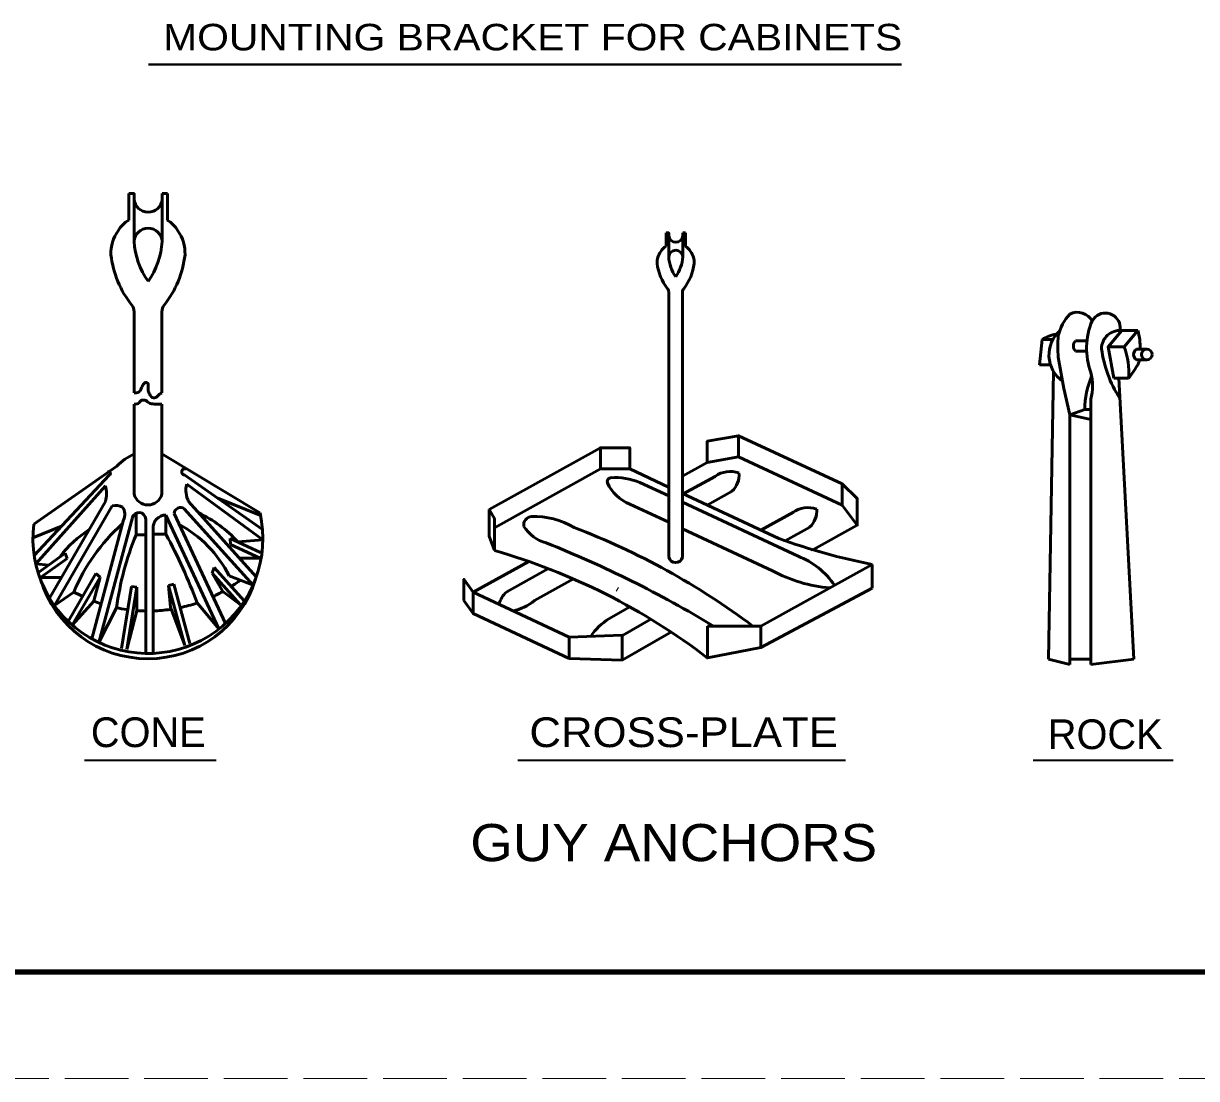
# Model space of a CAD drawing. Extents: x 12366 to 13046, y 9129 to 9570.
# Drawn here: x 12526.1 to 12636.6, y 9129.5 to 9228.9 of the extents above; entities that cross this region are included whole.
import ezdxf
from ezdxf.enums import TextEntityAlignment as Align

# ---------------------------------------------------------------- set-up
doc = ezdxf.new("R2010")
doc.units = 0
doc.linetypes.add('LONG_DASHED', pattern=[7.5, 6, -1.5])
doc.layers.add('1', color=7, linetype='Continuous', lineweight=53)
doc.layers.add('61', color=7, linetype='Continuous', lineweight=35)

msp = doc.modelspace()

# ---------------------------------------------------------------- linework, layer by layer
at = {"layer": '1', "lineweight": 40}
msp.add_line((12537.897, 9225.048), (12608.824, 9225.048), dxfattribs=at)
at = {"layer": '1'}
for p, q in [((12536.03, 9212.87), (12536.03, 9210.37)), ((12539.168, 9212.363), (12539.168, 9212.87)), ((12539.168, 9212.87), (12539.668, 9212.87)), ((12539.668, 9212.87), (12539.668, 9210.37)), ((12536.53, 9212.369), (12536.53, 9208.369)), ((12539.168, 9212.363), (12539.168, 9208.363)), ((12586.645, 9209.166), (12586.645, 9207.916)), ((12586.895, 9208.916), (12586.895, 9206.916)), ((12588.215, 9208.913), (12588.215, 9209.166)), ((12588.215, 9209.166), (12588.465, 9209.166)), ((12588.215, 9208.913), (12588.215, 9206.913)), ((12588.465, 9209.166), (12588.465, 9207.916)), ((12586.895, 9203.606), (12586.895, 9178.606)), ((12588.203, 9203.606), (12588.203, 9178.606)), ((12536.53, 9201.748), (12536.53, 9194.107)), ((12539.146, 9201.748), (12539.146, 9194.107)), ((12622.067, 9199.115), (12621.828, 9196.734)), ((12623.067, 9199.115), (12622.067, 9199.115)), ((12626.299, 9198.994), (12625.223, 9198.994)), ((12626.227, 9198.037), (12625.223, 9198.037)), ((12631.955, 9198.21), (12630.955, 9198.21)), ((12622.823, 9196.734), (12621.828, 9196.734)), ((12631.955, 9197.21), (12630.955, 9197.21)), ((12622.678, 9169.017), (12623.151, 9196.113)), ((12629.317, 9195.482), (12628.817, 9195.482)), ((12630.704, 9169.018), (12629.317, 9195.482)), ((12629.317, 9195.482), (12630.22, 9195.482)), ((12536.529, 9184.541), (12536.529, 9193.041)), ((12539.147, 9184.541), (12539.147, 9193.041)), ((12626.678, 9168.517), (12626.678, 9193.517)), ((12624.678, 9168.517), (12624.678, 9192.017)), ((12624.678, 9192.017), (12626.678, 9191.592)), ((12593.485, 9190.065), (12603.228, 9185.522)), ((12580.469, 9188.93), (12569.973, 9183.112)), ((12539.131, 9188.351), (12548.363, 9182.804)), ((12590.53, 9187.544), (12588.203, 9186.255)), ((12590.53, 9187.544), (12593.485, 9188.065)), ((12593.485, 9188.065), (12603.228, 9183.522)), ((12534.891, 9187.204), (12527.083, 9181.737)), ((12534.181, 9186.351), (12527.117, 9178.777)), ((12541.315, 9186.351), (12548.632, 9181.228)), ((12580.469, 9186.93), (12570.473, 9181.389)), ((12583.219, 9186.93), (12586.889, 9185.219)), ((12591.258, 9186.233), (12588.268, 9184.575)), ((12533.831, 9185.351), (12527.265, 9177.988)), ((12541.484, 9185.483), (12548.665, 9180.265)), ((12584.177, 9185.656), (12586.906, 9184.383)), ((12603.228, 9185.522), (12603.228, 9183.522)), ((12548.37, 9182.583), (12544.413, 9184.182)), ((12588.203, 9184.606), (12597.266, 9180.379)), ((12592.864, 9184.836), (12590.509, 9183.531)), ((12533.831, 9183.851), (12528.575, 9174.748)), ((12534.466, 9183.452), (12529.037, 9174.049)), ((12541.261, 9183.179), (12547.737, 9175.987)), ((12541.665, 9183.851), (12548.034, 9176.778)), ((12583.226, 9183.617), (12586.895, 9181.905)), ((12588.185, 9183.787), (12599.079, 9178.707)), ((12535.538, 9182.125), (12532.536, 9170.924)), ((12536.378, 9182.366), (12533.218, 9170.573)), ((12536.711, 9180.711), (12536.711, 9182.816)), ((12537.622, 9182.214), (12537.622, 9169.541)), ((12539.532, 9182.588), (12544.528, 9171.873)), ((12540.292, 9182.731), (12545.127, 9172.365)), ((12598.641, 9182.867), (12595.576, 9181.168)), ((12526.981, 9180.44), (12529.689, 9181.534)), ((12536.711, 9180.711), (12537.622, 9180.711)), ((12538.332, 9181.271), (12538.332, 9169.541)), ((12588.203, 9181.296), (12596.675, 9177.345)), ((12600.189, 9181.438), (12597.883, 9180.16)), ((12545.587, 9180.387), (12548.439, 9179.057)), ((12545.587, 9180.387), (12545.614, 9179.822)), ((12545.614, 9179.822), (12548.408, 9178.519)), ((12548.665, 9180.265), (12546.292, 9180.058)), ((12527.426, 9177.101), (12530.05, 9179.007)), ((12527.72, 9176.697), (12530.214, 9178.508)), ((12530.05, 9179.007), (12530.214, 9178.508)), ((12548.408, 9178.519), (12546.466, 9178.519)), ((12527.265, 9177.988), (12528.498, 9177.88)), ((12544.07, 9177.646), (12543.882, 9177.108)), ((12544.07, 9177.646), (12546.901, 9174.501)), ((12575.567, 9177.535), (12571.63, 9175.353)), ((12606.057, 9177.935), (12606.057, 9175.685)), ((12527.72, 9176.697), (12529.73, 9176.697)), ((12530.331, 9172.558), (12532.939, 9177.074)), ((12530.709, 9172.212), (12533.32, 9176.733)), ((12533.32, 9176.733), (12532.725, 9174.514)), ((12532.939, 9177.074), (12533.32, 9176.733)), ((12543.882, 9177.108), (12546.53, 9174.167)), ((12544.892, 9175.376), (12543.882, 9177.108)), ((12547.737, 9175.987), (12545.484, 9176.872)), ((12577.936, 9176.561), (12574.262, 9174.525)), ((12529.037, 9174.049), (12530.858, 9175.328)), ((12536.278, 9175.861), (12535.35, 9170.003)), ((12536.772, 9175.783), (12535.844, 9169.924)), ((12536.278, 9175.861), (12536.772, 9175.783)), ((12536.772, 9175.783), (12536.772, 9173.562)), ((12540.266, 9176.079), (12539.783, 9175.949)), ((12539.783, 9175.949), (12541.299, 9170.292)), ((12539.783, 9175.949), (12539.961, 9173.915)), ((12540.266, 9176.079), (12541.766, 9170.48)), ((12546.53, 9174.167), (12544.892, 9175.376)), ((12568.459, 9175.31), (12577.522, 9171.084)), ((12568.459, 9175.31), (12568.459, 9173.31)), ((12530.709, 9172.212), (12532.753, 9174.49)), ((12544.528, 9171.873), (12542.47, 9174.303)), ((12533.218, 9170.573), (12534.879, 9173.845)), ((12535.844, 9169.924), (12536.772, 9173.562)), ((12541.299, 9170.292), (12539.961, 9173.915)), ((12583.226, 9173.941), (12581.27, 9172.809)), ((12585.214, 9172.781), (12582.544, 9171.235)), ((12595.562, 9172.118), (12595.562, 9170.118)), ((12577.522, 9171.084), (12582.519, 9171.258)), ((12577.522, 9171.084), (12577.522, 9169.084)), ((12587.157, 9171.596), (12582.519, 9168.909)), ((12582.519, 9171.258), (12582.519, 9168.909)), ((12577.522, 9169.084), (12582.519, 9168.909)), ((12622.678, 9169.017), (12624.678, 9168.517)), ((12624.678, 9169.017), (12626.678, 9169.017)), ((12626.678, 9168.517), (12630.704, 9169.018))]:
    msp.add_line(p, q, dxfattribs=at)
at = {"layer": '1', "lineweight": 13}
for p, q in [((12600.486, 9179.316), (12600.324, 9179.222)), ((12581.956, 9175.403), (12582.168, 9175.746))]:
    msp.add_line(p, q, dxfattribs=at)
at = {"layer": '1', "lineweight": 35}
for p, q in [((12531.844, 9159.487), (12544.266, 9159.487)), ((12572.686, 9159.487), (12603.553, 9159.487)), ((12621.245, 9159.487), (12634.419, 9159.487))]:
    msp.add_line(p, q, dxfattribs=at)
at = {"layer": '1'}
for points in [[(12536.53, 9212.369), (12536.53, 9212.87), (12536.03, 9212.87)], [(12586.895, 9208.916), (12586.895, 9209.166), (12586.645, 9209.166)], [(12628.817, 9195.482), (12628.296, 9198.436), (12629.796, 9198.436), (12631.082, 9199.968)], [(12628.296, 9198.436), (12629.582, 9199.968), (12631.082, 9199.968)], [(12624.678, 9192.017), (12624.123, 9194.513), (12623.602, 9197.468)], [(12624.678, 9192.017), (12626.088, 9192.53), (12626.678, 9192.53)], [(12590.53, 9187.544), (12590.53, 9189.544), (12593.485, 9190.065), (12593.485, 9188.065)], [(12603.236, 9185.116), (12603.228, 9185.522), (12604.666, 9184.133), (12604.666, 9181.633)], [(12569.973, 9183.112), (12570.473, 9182.246), (12570.473, 9179.246)], [(12569.973, 9183.112), (12569.973, 9180.612), (12570.473, 9179.246)], [(12603.228, 9183.522), (12604.666, 9181.633), (12600.486, 9179.316)], [(12539.532, 9182.588), (12539.532, 9180.782), (12538.332, 9180.782)], [(12573.706, 9178.219), (12568.459, 9175.31), (12567.598, 9176.539), (12567.598, 9174.539)], [(12606.057, 9177.935), (12595.562, 9172.118), (12590.562, 9172.118)], [(12590.562, 9172.118), (12590.562, 9169.118), (12595.562, 9170.118), (12606.057, 9175.685)], [(12567.598, 9174.539), (12568.459, 9173.31), (12577.522, 9169.084)]]:
    msp.add_lwpolyline(points, dxfattribs=at)
msp.add_lwpolyline([(12583.219, 9186.93), (12583.219, 9188.93), (12580.469, 9188.93), (12580.469, 9186.93)], close=True, dxfattribs=at)
msp.add_circle((12631.936, 9197.714), 0.5, dxfattribs=at)
for centre, radius, start, end in [((12537.849, 9212.441), 1.321, 183.14868, 356.60343), ((12537.296, 9208.104), 2.595, 119.19068, 150.80932), ((12537.849, 9208.29), 1.321, 3.15687, 176.59703), ((12538.38, 9208.104), 2.595, 29.19068, 60.80932), ((12538.005, 9207.241), 3.659, 144.42176, 182.06662), ((12543.742, 9208.792), 7.224, 183.35766, 215.34932), ((12531.957, 9208.786), 7.224, 324.65068, 356.64234), ((12537.67, 9207.241), 3.659, 357.93338, 35.57824), ((12587.555, 9208.952), 0.661, 183.14868, 356.60343), ((12587.633, 9206.352), 1.829, 144.42176, 182.06662), ((12587.278, 9206.783), 1.298, 119.19068, 150.80932), ((12587.555, 9206.876), 0.661, 3.15687, 176.59703), ((12587.82, 9206.783), 1.298, 29.19068, 60.80932), ((12587.466, 9206.352), 1.829, 357.93338, 35.57824), ((12543.627, 9208.177), 9.339, 186.56595, 218.44896), ((12532.049, 9208.177), 9.339, 321.55104, 353.43405), ((12590.444, 9206.82), 4.669, 186.56595, 218.44896), ((12590.501, 9207.127), 3.612, 183.35766, 215.34932), ((12584.609, 9207.124), 3.612, 324.65068, 356.64234), ((12584.655, 9206.82), 4.669, 321.55104, 353.43405), ((12586.395, 9203.606), 0.5, 0, 38.44896), ((12588.703, 9203.606), 0.5, 141.55104, 180), ((12535.53, 9201.748), 1, 0, 38.44896), ((12540.146, 9201.748), 1, 141.55104, 180), ((12625.398, 9200.116), 1.576, 27.27122, 117.20122), ((12627.798, 9198.572), 4.29, 136.6517, 167.95246), ((12632.799, 9198.312), 6.537, 156.78247, 200.56684), ((12630.274, 9198.37), 4.297, 137.75004, 144.12043), ((12628.029, 9200.203), 1.411, 354.19595, 131.52888), ((12623.942, 9196.256), 3.419, 98.89517, 123.27294), ((12625.726, 9197.667), 3.008, 130.0252, 235.18403), ((12633.137, 9198.468), 9.587, 174.01262, 185.98737), ((12629.403, 9198.248), 1.73, 84.04734, 179.89391), ((12625.773, 9198.366), 5.545, 358.55245, 16.7912), ((12625.685, 9198.515), 0.665, 133.97941, 226.02058), ((12623.457, 9196.02), 6.784, 355.44941, 20.86555), ((12639.49, 9199.924), 11.935, 188.05699, 211.90806), ((12631.31, 9197.71), 0.613, 125.33791, 234.66209), ((12623.067, 9201.233), 9.179, 321.19678, 333.99968), ((12634.442, 9192.444), 8.355, 157.16459, 179.40955), ((12621.102, 9194.767), 5.714, 347.36391, 12.63609), ((12539.59, 9182.237), 6.837, 116.58954, 133.41014), ((12534.137, 9186.511), 0.166, 285.47106, 119.84894), ((12541.305, 9186.647), 0.296, 72.34222, 272.05741), ((12592.697, 9184.211), 2.482, 70.73362, 125.44724), ((12591.465, 9186.358), 2.06, 312.2199, 5.43688), ((12530.922, 9184.601), 3.004, 345.54353, 14.45647), ((12543.756, 9184.909), 2.343, 165.83192, 206.84011), ((12581.49, 9185.731), 0.383, 85.12517, 207.35251), ((12584.667, 9187.238), 3.897, 204.55458, 248.28903), ((12581.852, 9180.1), 6.022, 67.29002, 93.88305), ((12537.838, 9184.898), 1.357, 195.24731, 344.75269), ((12534.813, 9182.09), 1.406, 63.18198, 104.27978), ((12534.322, 9182.648), 1.323, 336.72582, 31.75765), ((12540.906, 9182.676), 0.616, 54.79805, 174.78973), ((12600.018, 9180.811), 2.482, 70.73362, 125.44724), ((12598.786, 9182.959), 2.06, 312.2199, 5.43688), ((12537.832, 9180.374), 10.833, 172.76636, 12.86069), ((12536.988, 9182.186), 0.635, 2.53809, 163.55027), ((12539.512, 9181.401), 1.187, 89.05434, 186.28866), ((12537.699, 9172.326), 11.559, 41.97741, 64.76098), ((12574.03, 9181.646), 0.798, 94.88611, 188.90189), ((12574.241, 9175.16), 7.287, 59.08543, 92.19679), ((12538.317, 9171.928), 11.065, 122.96526, 142.37873), ((12546.995, 9168.693), 17.448, 131.72438, 157.64771), ((12562.336, 9170.193), 27.699, 157.68458, 172.42454), ((12494.513, 9156.456), 51.171, 20.41201, 28.38414), ((12535.191, 9171.597), 11.567, 27.13242, 61.23505), ((12576.394, 9183.572), 3.76, 213.03543, 254.05828), ((12553.621, 9117.355), 68.533, 53.04115, 69.17556), ((12536.675, 9082.392), 104.955, 58.74865, 68.37109), ((12617.677, 9236.759), 59.961, 250.09888, 258.8259), ((12553.808, 9121.208), 60.383, 52.50633, 73.9788), ((12587.549, 9178.783), 0.678, 195.19877, 344.80123), ((12596.444, 9171.888), 7.31, 33.93256, 68.86981), ((12537.832, 9179.635), 10.594, 196.98242, 343.01758), ((12537.832, 9188.041), 14.5, 302.79246, 306.95206), ((12603.128, 9189.054), 13.37, 241.1379, 265.46719), ((12537.832, 9188.041), 14.5, 241.25089, 244.7288), ((12537.832, 9188.041), 14.5, 294.68825, 298.86032), ((12573.032, 9173.711), 2.158, 130.48502, 167.67788), ((12537.832, 9188.041), 14.5, 249.43644, 252.21677), ((12537.832, 9188.041), 14.5, 282.12514, 288.50814), ((12571.093, 9178.507), 5.089, 282.65039, 308.50672), ((12537.832, 9188.041), 14.5, 258.07352, 262.19692), ((12537.832, 9188.041), 14.5, 265.78587, 269.16942), ((12537.832, 9188.041), 14.5, 271.8867, 278.3643), ((12584.096, 9168.154), 5.445, 121.25992, 146.56057)]:
    msp.add_arc(centre, radius, start, end, dxfattribs=at)
for points in [[(12536.53, 9194.107), (12536.97, 9194.173), (12537.227, 9194.558), (12537.485, 9194.987), (12537.742, 9195.073), (12537.87, 9194.644), (12537.87, 9194.301), (12537.999, 9193.959), (12538.256, 9193.659), (12538.641, 9193.702), (12539.027, 9194.044), (12539.146, 9194.107)], [(12536.529, 9193.041), (12536.809, 9193.055), (12537.007, 9193.154), (12537.188, 9193.384), (12537.369, 9193.417), (12537.699, 9193.335), (12537.88, 9193.187), (12538.291, 9193.055), (12538.604, 9193.039), (12539.147, 9193.041)]]:
    msp.add_spline(points, degree=3, dxfattribs=at)
at = {"layer": '61', "lineweight": 158}
msp.add_line((13035.052, 9139.493), (12395.992, 9139.513), dxfattribs=at)
at = {"layer": '61', "linetype": 'LONG_DASHED', "lineweight": 13}
msp.add_line((13045.992, 9129.513), (12365.932, 9129.493), dxfattribs=at)

# ---------------------------------------------------------------- texts
at = {"layer": '1', "width": 1.15}
msp.add_text('MOUNTING BRACKET FOR CABINETS', height=2.5, dxfattribs=at).set_placement((12539.267, 9226.368))
at = {"layer": '1'}
for s, p in [('CONE', (12537.867, 9160.722)), ('ROCK', (12628.02, 9160.534))]:
    msp.add_text(s, height=2.8, dxfattribs=at).set_placement(p, align=Align.CENTER)
at = {"layer": '1', "width": 1.1}
for s, height, p in [('CROSS-PLATE', 2.8, (12588.308, 9160.722)), ('GUY ANCHORS', 3.5, (12587.367, 9149.974))]:
    msp.add_text(s, height=height, dxfattribs=at).set_placement(p, align=Align.CENTER)

doc.saveas('drawing.dxf')
